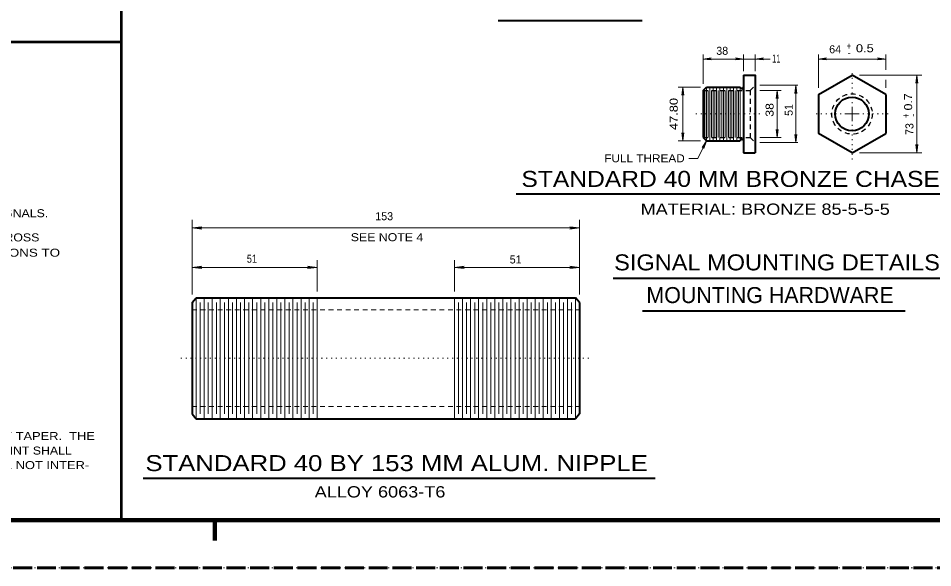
# Model space of a CAD drawing. Extents: x 312583 to 312854, y 144419 to 144597.
# Drawn here: x 312708.7 to 312795.5, y 144418.6 to 144470.8 of the extents above; entities that cross this region are included whole.
import ezdxf
from ezdxf.enums import TextEntityAlignment as Align

# ---------------------------------------------------------------- set-up
doc = ezdxf.new("R2010")
doc.units = 0
doc.header["$LTSCALE"] = 0.3
for name, pattern in [('DOTTED', [1.5, 0.3, -1.2]), ('LONG_DASHED', [7.5, 6, -1.5]), ('SHORT_DASHED', [2.7, 1.5, -1.2])]:
    doc.linetypes.add(name, pattern=pattern)
for name, color, linetype, lineweight in [('1', 7, 'Continuous', 35), ('2', 7, 'Continuous', 13), ('62', 7, 'DOTTED', 13), ('63', 7, 'LONG_DASHED', 60)]:
    doc.layers.add(name, color=color, linetype=linetype, lineweight=lineweight)

msp = doc.modelspace()

# ---------------------------------------------------------------- linework, layer by layer
at = {"layer": '1', "lineweight": 53}
for p, q in [((312718.4834, 144423.0846), (312718.4834, 144502.9994)), ((312718.4834, 144468.5083), (312616.5, 144468.5083))]:
    msp.add_line(p, q, dxfattribs=at)
at = {"layer": '1', "lineweight": 40}
for p, q in [((312777.5492, 144465.3677), (312777.5492, 144457.9924)), ((312784.6562, 144463.52), (312787.8532, 144465.3677)), ((312791.0502, 144463.52), (312787.8532, 144465.3677)), ((312773.7159, 144463.911), (312774.0379, 144464.233)), ((312773.7159, 144463.911), (312773.7159, 144459.4414)), ((312774.0379, 144464.233), (312777.2272, 144464.233)), ((312784.6562, 144463.52), (312784.6562, 144459.8324)), ((312791.0502, 144463.52), (312791.0502, 144459.8324)), ((312773.7159, 144459.4414), (312774.0379, 144459.1194)), ((312787.8532, 144457.9847), (312784.6562, 144459.8324)), ((312787.8532, 144457.9847), (312791.0502, 144459.8324)), ((312774.0379, 144459.1194), (312777.2272, 144459.1194)), ((312777.5492, 144457.9924), (312778.6685, 144457.9924)), ((312725.1837, 144443.7658), (312725.5594, 144444.2258)), ((312725.1837, 144443.7658), (312725.1837, 144433.1858)), ((312725.5594, 144444.2258), (312761.5927, 144444.2258)), ((312761.9837, 144443.7658), (312761.5927, 144444.2258)), ((312761.9837, 144443.7658), (312761.9837, 144433.1858)), ((312725.1837, 144433.1858), (312725.5594, 144432.7258)), ((312761.9837, 144433.1858), (312761.5927, 144432.7258)), ((312725.5594, 144432.7258), (312761.5927, 144432.7258))]:
    msp.add_line(p, q, dxfattribs=at)
at = {"layer": '1', "linetype": 'SHORT_DASHED', "lineweight": 25}
for p, q in [((312778.1779, 144463.911), (312778.6532, 144464.394)), ((312773.7159, 144463.911), (312778.1779, 144463.911)), ((312778.1779, 144463.911), (312778.1779, 144459.4414)), ((312773.7159, 144459.4414), (312778.1779, 144459.4414)), ((312778.1779, 144459.4414), (312778.6532, 144458.966))]:
    msp.add_line(p, q, dxfattribs=at)
at = {"layer": '1', "lineweight": 13}
for p, q in [((312773.8769, 144463.911), (312773.8769, 144459.4414)), ((312774.0379, 144464.233), (312774.0379, 144459.1194)), ((312774.1912, 144463.911), (312774.1912, 144459.4414)), ((312774.3522, 144464.233), (312774.3522, 144459.1194)), ((312774.5132, 144463.911), (312774.5132, 144459.4414)), ((312774.6742, 144464.233), (312774.6742, 144459.1194)), ((312774.8352, 144463.911), (312774.8352, 144459.4414)), ((312774.9962, 144464.233), (312774.9962, 144459.1194)), ((312775.1495, 144463.911), (312775.1495, 144459.4414)), ((312775.3105, 144464.233), (312775.3105, 144459.1194)), ((312775.4715, 144463.911), (312775.4715, 144459.4414)), ((312775.6325, 144464.233), (312775.6325, 144459.1194)), ((312775.7935, 144463.911), (312775.7935, 144459.4414)), ((312775.9545, 144464.233), (312775.9545, 144459.1194)), ((312776.1079, 144463.911), (312776.1079, 144459.4414)), ((312776.2689, 144464.233), (312776.2689, 144459.1194)), ((312776.4299, 144463.911), (312776.4299, 144459.4414)), ((312776.5909, 144464.233), (312776.5909, 144459.1194)), ((312776.7519, 144463.911), (312776.7519, 144459.4414)), ((312776.9129, 144464.233), (312776.9129, 144459.1194)), ((312777.0662, 144463.911), (312777.0662, 144459.4414)), ((312777.2272, 144464.233), (312777.2272, 144459.1194)), ((312725.5594, 144444.2258), (312725.5594, 144432.7258)), ((312725.9504, 144443.7658), (312725.9504, 144433.1858)), ((312726.326, 144444.2258), (312726.326, 144432.7258)), ((312726.717, 144443.7658), (312726.717, 144433.1858)), ((312727.0927, 144444.2258), (312727.0927, 144432.7258)), ((312727.4837, 144443.7658), (312727.4837, 144433.1858)), ((312727.8594, 144444.2258), (312727.8594, 144432.7258)), ((312728.2504, 144443.7658), (312728.2504, 144433.1858)), ((312728.626, 144444.2258), (312728.626, 144432.7258)), ((312729.017, 144443.7658), (312729.017, 144433.1858)), ((312729.3927, 144444.2258), (312729.3927, 144432.7258)), ((312729.7837, 144443.7658), (312729.7837, 144433.1858)), ((312730.1594, 144444.2258), (312730.1594, 144432.7258)), ((312730.5504, 144443.7658), (312730.5504, 144433.1858)), ((312730.926, 144444.2258), (312730.926, 144432.7258)), ((312731.317, 144443.7658), (312731.317, 144433.1858)), ((312731.6927, 144444.2258), (312731.6927, 144432.7258)), ((312732.0837, 144443.7658), (312732.0837, 144433.1858)), ((312732.4594, 144444.2258), (312732.4594, 144432.7258)), ((312732.8504, 144443.7658), (312732.8504, 144433.1858)), ((312733.226, 144444.2258), (312733.226, 144432.7258)), ((312733.617, 144443.7658), (312733.617, 144433.1858)), ((312733.9927, 144444.2258), (312733.9927, 144432.7258)), ((312734.3837, 144443.7658), (312734.3837, 144433.1858)), ((312734.7594, 144444.2258), (312734.7594, 144432.7258)), ((312735.1504, 144443.7658), (312735.1504, 144433.1858)), ((312735.526, 144444.2258), (312735.526, 144432.7258)), ((312735.917, 144443.7658), (312735.917, 144433.1858)), ((312736.2927, 144444.2258), (312736.2927, 144432.7258)), ((312736.6837, 144443.7658), (312736.6837, 144433.1858)), ((312737.0594, 144444.2258), (312737.0594, 144432.7258)), ((312750.0927, 144444.2258), (312750.0927, 144432.7258)), ((312750.4837, 144443.7658), (312750.4837, 144433.1858)), ((312750.8594, 144444.2258), (312750.8594, 144432.7258)), ((312751.2504, 144443.7658), (312751.2504, 144433.1858)), ((312751.626, 144444.2258), (312751.626, 144432.7258)), ((312752.017, 144443.7658), (312752.017, 144433.1858)), ((312752.3927, 144444.2258), (312752.3927, 144432.7258)), ((312752.7837, 144443.7658), (312752.7837, 144433.1858)), ((312753.1594, 144444.2258), (312753.1594, 144432.7258)), ((312753.5504, 144443.7658), (312753.5504, 144433.1858)), ((312753.926, 144444.2258), (312753.926, 144432.7258)), ((312754.317, 144443.7658), (312754.317, 144433.1858)), ((312754.6927, 144444.2258), (312754.6927, 144432.7258)), ((312755.0837, 144443.7658), (312755.0837, 144433.1858)), ((312755.4594, 144444.2258), (312755.4594, 144432.7258)), ((312755.8504, 144443.7658), (312755.8504, 144433.1858)), ((312756.226, 144444.2258), (312756.226, 144432.7258)), ((312756.617, 144443.7658), (312756.617, 144433.1858)), ((312756.9927, 144444.2258), (312756.9927, 144432.7258)), ((312757.3837, 144443.7658), (312757.3837, 144433.1858)), ((312757.7594, 144444.2258), (312757.7594, 144432.7258)), ((312758.1504, 144443.7658), (312758.1504, 144433.1858)), ((312758.526, 144444.2258), (312758.526, 144432.7258)), ((312758.917, 144443.7658), (312758.917, 144433.1858)), ((312759.2927, 144444.2258), (312759.2927, 144432.7258)), ((312759.6837, 144443.7658), (312759.6837, 144433.1858)), ((312760.0594, 144444.2258), (312760.0594, 144432.7258)), ((312760.4504, 144443.7658), (312760.4504, 144433.1858)), ((312760.826, 144444.2258), (312760.826, 144432.7258)), ((312761.217, 144443.7658), (312761.217, 144433.1858)), ((312761.5927, 144444.2258), (312761.5927, 144432.7258))]:
    msp.add_line(p, q, dxfattribs=at)
at = {"layer": '1', "linetype": 'SHORT_DASHED', "lineweight": 13}
for p, q in [((312725.1837, 144443.0834), (312761.9837, 144443.0834)), ((312725.1837, 144433.8834), (312761.9837, 144433.8834))]:
    msp.add_line(p, q, dxfattribs=at)
at = {"layer": '1', "linetype": 'DOTTED', "lineweight": 13}
msp.add_line((312724.1104, 144438.4834), (312762.9727, 144438.4834), dxfattribs=at)
at = {"layer": '1', "lineweight": 158}
for p, q in [((312616.5, 144423.0846), (312849, 144423.0846)), ((312727.35, 144421.1646), (312727.35, 144423.0846))]:
    msp.add_line(p, q, dxfattribs=at)
at = {"layer": '1', "lineweight": 40}
msp.add_lwpolyline([(312777.5492, 144465.3677), (312778.6685, 144465.3677), (312778.6685, 144457.9924)], dxfattribs=at)
at = {"layer": '1', "linetype": 'SHORT_DASHED', "lineweight": 25}
msp.add_circle((312787.8532, 144461.6775), 1.9167, dxfattribs=at)
at = {"layer": '1', "lineweight": 40}
msp.add_circle((312787.8532, 144461.6775), 1.5972, dxfattribs=at)
for centre, start, end in [((312777.3908, 144464.233), 180, 0), ((312777.3908, 144459.1219), 0, 180)]:
    msp.add_arc(centre, 0.1597, start, end, dxfattribs=at)
at = {"layer": '2', "lineweight": 40}
for p, q in [((312754.2336, 144470.5437), (312767.9188, 144470.5437)), ((312755.9574, 144454.0747), (312805.1095, 144454.0747)), ((312765.171, 144446.0784), (312796.7688, 144446.0784)), ((312767.9654, 144442.9734), (312792.8997, 144442.9734)), ((312720.5265, 144427.0872), (312769.1574, 144427.0872))]:
    msp.add_line(p, q, dxfattribs=at)
at = {"layer": '2'}
for p, q in [((312773.7159, 144464.5244), (312773.7159, 144467.3304)), ((312773.7159, 144466.8934), (312774.4825, 144466.993)), ((312774.4825, 144466.993), (312774.2372, 144466.8934)), ((312776.7825, 144466.993), (312777.0279, 144466.8934)), ((312777.5492, 144466.8934), (312776.7825, 144466.993)), ((312777.5492, 144465.7434), (312777.5492, 144467.3304)), ((312778.6685, 144465.7434), (312778.6685, 144467.3304)), ((312778.6685, 144466.8934), (312779.4352, 144466.993)), ((312779.4352, 144466.993), (312779.1899, 144466.8934)), ((312784.6562, 144464.164), (312784.6562, 144467.3304)), ((312784.6562, 144466.8934), (312785.4305, 144466.993)), ((312785.4305, 144466.993), (312785.1852, 144466.8934)), ((312790.2759, 144466.993), (312790.5212, 144466.8934)), ((312791.0502, 144466.8934), (312790.2759, 144466.993)), ((312791.0502, 144465.8737), (312791.0502, 144467.3304)), ((312777.5492, 144466.8934), (312773.7159, 144466.8934)), ((312773.7159, 144466.8934), (312774.4825, 144466.8014)), ((312774.4825, 144466.8014), (312774.2372, 144466.8934)), ((312776.7825, 144466.8014), (312777.0279, 144466.8934)), ((312777.5492, 144466.8934), (312776.7825, 144466.8014)), ((312777.5492, 144466.8934), (312780.0792, 144466.8934)), ((312778.6685, 144466.8934), (312779.4352, 144466.8014)), ((312779.4352, 144466.8014), (312779.1899, 144466.8934)), ((312791.0502, 144466.8934), (312784.6562, 144466.8934)), ((312784.6562, 144466.8934), (312785.4305, 144466.8014)), ((312785.4305, 144466.8014), (312785.1852, 144466.8934)), ((312790.2759, 144466.8014), (312790.5212, 144466.8934)), ((312791.0502, 144466.8934), (312790.2759, 144466.8014)), ((312788.5585, 144465.3677), (312794.4849, 144465.3677)), ((312794.0172, 144465.3677), (312793.9252, 144464.5934)), ((312794.0172, 144457.9847), (312794.0172, 144465.3677)), ((312794.0172, 144465.3677), (312794.1092, 144464.5934)), ((312779.0979, 144464.394), (312782.7089, 144464.394)), ((312782.5095, 144464.394), (312782.4175, 144463.6197)), ((312782.5095, 144458.966), (312782.5095, 144464.394)), ((312782.5095, 144464.394), (312782.6015, 144463.6197)), ((312791.0502, 144464.164), (312791.0502, 144464.9077)), ((312793.9252, 144464.5934), (312794.0172, 144464.8387)), ((312794.1092, 144464.5934), (312794.0172, 144464.8387)), ((312773.4705, 144464.233), (312771.3545, 144464.233)), ((312771.7839, 144464.233), (312771.6919, 144463.4664)), ((312771.6919, 144463.4664), (312771.7839, 144463.7117)), ((312771.7839, 144459.1194), (312771.7839, 144464.233)), ((312771.7839, 144464.233), (312771.8835, 144463.4664)), ((312771.8835, 144463.4664), (312771.7839, 144463.7117)), ((312779.0979, 144463.911), (312781.1142, 144463.911)), ((312780.7539, 144463.911), (312780.6542, 144463.1444)), ((312780.7539, 144459.4414), (312780.7539, 144463.911)), ((312780.7539, 144463.911), (312780.8459, 144463.1444)), ((312782.4175, 144463.6197), (312782.5095, 144463.865)), ((312782.6015, 144463.6197), (312782.5095, 144463.865)), ((312780.6542, 144463.1444), (312780.7539, 144463.3897)), ((312780.8459, 144463.1444), (312780.7539, 144463.3897)), ((312787.8532, 144461.68), (312787.8532, 144462.3624)), ((312787.8532, 144461.68), (312787.1709, 144461.68)), ((312787.8532, 144461.68), (312788.5355, 144461.68)), ((312787.8532, 144461.68), (312787.8532, 144460.9977)), ((312780.6542, 144460.208), (312780.7539, 144459.9627)), ((312780.7539, 144459.4414), (312780.6542, 144460.208)), ((312780.8459, 144460.208), (312780.7539, 144459.9627)), ((312780.7539, 144459.4414), (312780.8459, 144460.208)), ((312771.6919, 144459.8937), (312771.7839, 144459.6484)), ((312771.7839, 144459.1194), (312771.6919, 144459.8937)), ((312771.8835, 144459.8937), (312771.7839, 144459.6484)), ((312771.7839, 144459.1194), (312771.8835, 144459.8937)), ((312779.0979, 144459.4414), (312781.1142, 144459.4414)), ((312782.4175, 144459.7327), (312782.5095, 144459.4874)), ((312782.5095, 144458.966), (312782.4175, 144459.7327)), ((312782.6015, 144459.7327), (312782.5095, 144459.4874)), ((312782.5095, 144458.966), (312782.6015, 144459.7327)), ((312773.4705, 144459.1194), (312771.3545, 144459.1194)), ((312774.0379, 144459.1194), (312773.6085, 144458.4754)), ((312773.6085, 144458.4754), (312773.8079, 144458.6517)), ((312774.0379, 144459.1194), (312773.7849, 144458.391)), ((312773.7849, 144458.391), (312773.8079, 144458.6517)), ((312779.0979, 144458.966), (312782.7089, 144458.966)), ((312793.9252, 144458.759), (312794.0172, 144458.5137)), ((312794.0172, 144457.9847), (312793.9252, 144458.759)), ((312794.1092, 144458.759), (312794.0172, 144458.5137)), ((312794.0172, 144457.9847), (312794.1092, 144458.759)), ((312788.5585, 144457.9847), (312794.4849, 144457.9847)), ((312725.1837, 144444.5324), (312725.1837, 144451.6088)), ((312761.9837, 144444.5324), (312761.9837, 144451.6088)), ((312725.1837, 144450.8498), (312726.1114, 144450.9648)), ((312725.1837, 144450.8498), (312761.9837, 144450.8498)), ((312725.1837, 144450.8498), (312726.1114, 144450.7271)), ((312726.1114, 144450.9648), (312725.8124, 144450.8498)), ((312726.1114, 144450.7271), (312725.8124, 144450.8498)), ((312761.056, 144450.9648), (312761.3474, 144450.8498)), ((312761.9837, 144450.8498), (312761.056, 144450.9648)), ((312761.056, 144450.7271), (312761.3474, 144450.8498)), ((312761.9837, 144450.8498), (312761.056, 144450.7271)), ((312725.1837, 144447.1008), (312726.1114, 144447.2158)), ((312725.1837, 144447.1008), (312737.0594, 144447.1008)), ((312725.1837, 144447.1008), (312726.1114, 144446.9858)), ((312726.1114, 144447.2158), (312725.8124, 144447.1008)), ((312726.1114, 144446.9858), (312725.8124, 144447.1008)), ((312736.1394, 144447.2158), (312736.4307, 144447.1008)), ((312737.0594, 144447.1008), (312736.1394, 144447.2158)), ((312736.1394, 144446.9858), (312736.4307, 144447.1008)), ((312737.0594, 144447.1008), (312736.1394, 144446.9858)), ((312737.0594, 144444.8084), (312737.0594, 144447.7908)), ((312750.0927, 144444.8084), (312750.0927, 144447.7908)), ((312750.0927, 144447.1008), (312751.0204, 144447.2158)), ((312750.0927, 144447.1008), (312761.9837, 144447.1008)), ((312750.0927, 144447.1008), (312751.0204, 144446.9858)), ((312751.0204, 144447.2158), (312750.729, 144447.1008)), ((312751.0204, 144446.9858), (312750.729, 144447.1008)), ((312761.056, 144447.2158), (312761.3474, 144447.1008)), ((312761.9837, 144447.1008), (312761.056, 144447.2158)), ((312761.056, 144446.9858), (312761.3474, 144447.1008)), ((312761.9837, 144447.1008), (312761.056, 144446.9858))]:
    msp.add_line(p, q, dxfattribs=at)
at = {"layer": '2', "linetype": 'DOTTED'}
for p, q in [((312787.8532, 144462.6997), (312787.8532, 144465.912)), ((312779.0979, 144461.68), (312772.9492, 144461.68)), ((312786.8335, 144461.68), (312784.1119, 144461.68)), ((312788.8729, 144461.68), (312791.5945, 144461.68)), ((312787.8532, 144460.6527), (312787.8532, 144457.3484))]:
    msp.add_line(p, q, dxfattribs=at)
at = {"layer": '2'}
msp.add_lwpolyline([(312772.3512, 144457.4557), (312773.2175, 144457.4557), (312774.0379, 144459.1194)], dxfattribs=at)
at = {"layer": '62'}
msp.add_lwpolyline([(312601.2, 144418.5846), (312853.5, 144418.5846), (312853.5, 144596.7846)], dxfattribs=at)
at = {"layer": '63'}
msp.add_line((312851.75, 144418.5846), (312583.526, 144418.5846), dxfattribs=at)

# ---------------------------------------------------------------- texts
at = {"layer": '2'}
for s, height, p in [('38', 0.76, (312774.9578, 144467.2926)), ('64', 0.76, (312785.6828, 144467.4376)), ('153', 0.76, (312742.5714, 144451.5843)), ('51 ', 0.76, (312755.3428, 144447.4767)), ('MOUNTING HARDWARE', 1.52, (312768.323, 144443.7161))]:
    msp.add_text(s, height=height, dxfattribs=at).set_placement(p)
for s, height, width, p in [('+', 0.6797, 0.8, (312787.5598, 144467.7914)), ('MATERIAL: BRONZE 85-5-5-5', 1.07, 1.2, (312779.6056, 144452.0989)), ('ALLOY 6063-T6', 1.07, 1.2, (312743.0255, 144425.2548))]:
    msp.add_text(s, height=height, dxfattribs=dict(at, width=width)).set_placement(p, align=Align.CENTER)
for s, height, width, p in [('0.5 ', 0.76, 1.2, (312788.2192, 144467.5347)), ('11', 0.76, 0.7, (312780.263, 144466.5609)), ('FULL THREAD', 0.76, 1.1, (312764.3221, 144457.085)), ('STANDARD 40 MM BRONZE CHASE NIPPLE', 1.52, 1.15, (312756.452, 144454.7456)), ('SUPPORTS FOR HIGHWAY SIGNS, LUMINAIRES & TRAFFIC SIGNALS. ', 0.76, 1.15, (312672.5508, 144451.8706)), ('PROVIDE SLOTS OR SERRATIONS IN FACE OF ELBOW AND CROSS  ', 0.76, 1.15, (312672.5508, 144449.5706)), ('SEE NOTE 4', 0.76, 1.15, (312740.2468, 144449.593)), ('TEE.  SLOTS TO BE  4 MM DEEP BY 5 MM WIDE.  SERRATIONS TO  ', 0.76, 1.25, (312672.4075, 144448.1188)), ('51', 0.76, 0.85, (312730.3766, 144447.5485)), ('SIGNAL MOUNTING DETAILS', 1.52, 1.1, (312765.2637, 144446.821)), ('JOINTS WILL BE PERMITTED TO PROVIDE THE NECESSARY TAPER.  THE  ', 0.76, 1.2, (312672.7118, 144430.7106)), ('MANUFACTURER SHALL DETERMINE THE LOCATION.  THE JOINT SHALL ', 0.76, 1.15, (312672.7118, 144429.3306)), ('STANDARD 40 BY 153 MM ALUM. NIPPLE', 1.52, 1.2, (312720.7446, 144427.7589)), ('PROVIDE FOR A MINIMUM OVERLAP OF 152 MM AND SHALL NOT INTER- ', 0.76, 1.2, (312672.7118, 144427.9506))]:
    msp.add_text(s, height=height, dxfattribs=dict(at, width=width)).set_placement(p)
msp.add_text('-', height=0.6797, dxfattribs=at).set_placement((312787.5943, 144467.1704), align=Align.CENTER)
for s, width, p in [('0.7', 1.15, (312793.5623, 144462.0108)), ('47.80', 1.2, (312771.2953, 144460.1418)), ('38 ', 1.15, (312780.4014, 144461.4106))]:
    msp.add_text(s, height=0.76, rotation=90, dxfattribs=dict(at, width=width)).set_placement(p)
for s, p in [('51 ', (312782.2184, 144461.4897)), ('73', (312793.686, 144459.6771))]:
    msp.add_text(s, height=0.76, rotation=90, dxfattribs=at).set_placement(p)
at = {"layer": '2', "width": 0.8}
msp.add_text('+', height=0.6797, rotation=90, dxfattribs=at).set_placement((312793.3057, 144461.5047), align=Align.CENTER)
at = {"layer": '2'}
msp.add_text('-', height=0.6797, rotation=90, dxfattribs=at).set_placement((312793.9343, 144461.5546), align=Align.CENTER)

doc.saveas('drawing.dxf')
